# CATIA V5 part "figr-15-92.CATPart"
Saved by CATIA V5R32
Part number: Part1
Bounding box of the stored display mesh (mm): x -40 to 40, y -60 to 60, z 0 to 2
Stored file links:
  D:\PROJECTS\Project 2022\CATIA V5 6R 2022\Resources\Part Files\c15_catia_v5_6r2022_prt\figr-15-92.CATPart
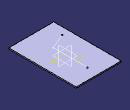
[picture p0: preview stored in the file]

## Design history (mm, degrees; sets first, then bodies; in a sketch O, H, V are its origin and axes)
SheetMetalParameters1: Thickness 2, BendRadius 4, KFactor 0.400515 {= log(min(100,max(20*SheetMetalParameters1.BendRadius,SheetMetalParameters1.Thickness)/SheetMetalParameters1.Thickness))/log(100)/2}, ReliefRadialLength 1, ReliefAxialLength 2, MinimumBendRadius 0
Body1 (main body)
  Sketch1 on xy-plane, origin (0, 0, 0), H (-1, 0, 0), V (0, -1, 0)
    line L1 (40, 60) -> (40, -60)
    line L2 (40, -60) -> (-40, -60)
    line L3 (-40, -60) -> (-40, 60)
    line L4 (-40, 60) -> (40, 60)
    length L4 = 80
    length L1 = 120
    vertical: L1 V, L3 V
    horizontal: L2 H, L4 H
    equidistance: L1 L3 O, L2 L4 O
  Wall1: Thickness 2, Profile Sketch1, OffsetValue 0
  Sketch2 on face of Wall1, origin (0, 0, 2), H (1, 0, 0), V (0, 1, 0)
    line L1 (0, 40.0798) -> (0, -21.0085)
    line L2 (0, -21.0085) -> (-27, -32)
    vertical: L1 V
